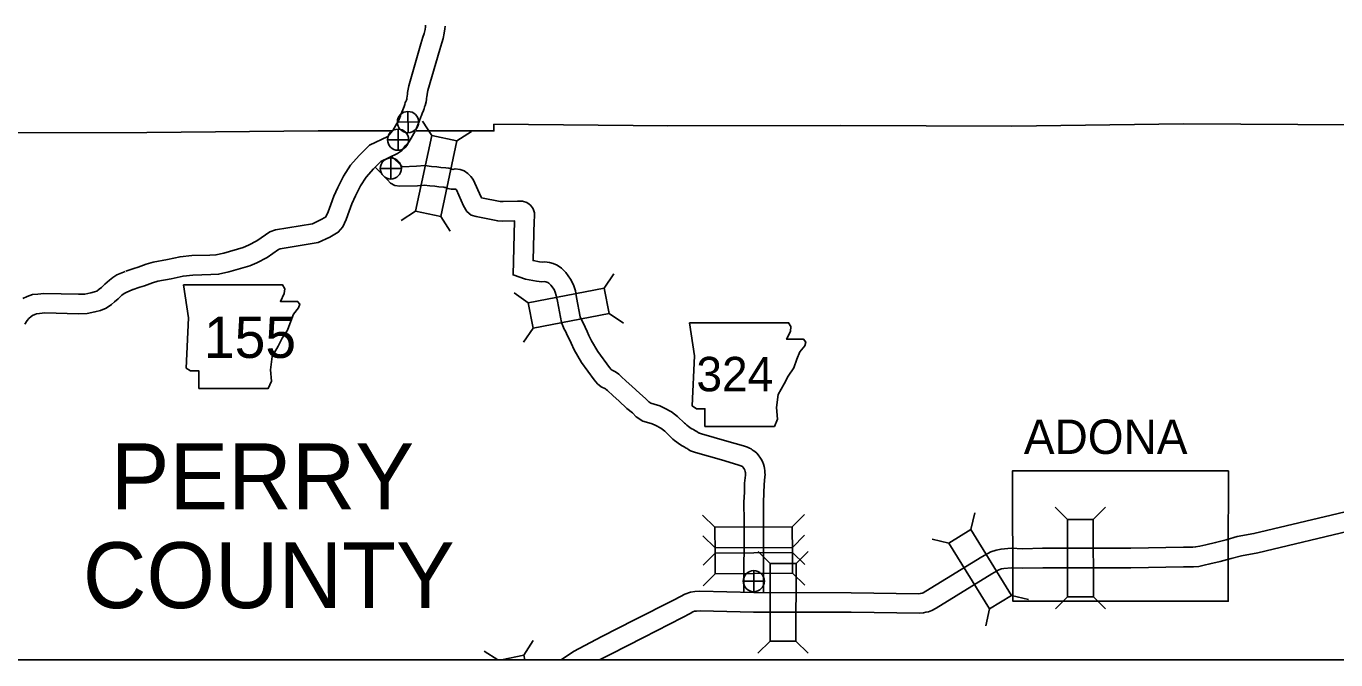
# Model space of a CAD drawing. Extents: x 1374139 to 1377472, y 1168351 to 1170484.
# Drawn here: x 1374727.2 to 1374928.1, y 1169604.3 to 1169701.5 of the extents above; entities that cross this region are included whole.
import ezdxf

# ---------------------------------------------------------------- set-up
doc = ezdxf.new("R2010")
doc.units = 0
doc.layers.add('26', color=7, linetype='Continuous')
doc.layers.add('Default', color=7, linetype='Continuous')

msp = doc.modelspace()

# ---------------------------------------------------------------- linework, layer by layer
at = {"layer": '26'}
msp.add_lwpolyline([(1374299.15, 1170388.77), (1375028.55, 1170388.77), (1375028.55, 1169604.28), (1374299.15, 1169604.28)], close=True, dxfattribs=at)
at = {"layer": 'Default'}
for p, q in [((1374785.8, 1169685.14), (1374785.73, 1169688.39)), ((1374784.14, 1169686.73), (1374787.39, 1169686.8)), ((1374784.25, 1169682.44), (1374784.25, 1169685.69)), ((1374789.42, 1169684.71), (1374787.99, 1169686.93)), ((1374782.62, 1169684.06), (1374785.87, 1169684.06)), ((1374793.29, 1169683.87), (1374795.51, 1169685.31)), ((1374781.51, 1169679.64), (1374784.76, 1169679.64)), ((1374783.14, 1169678.02), (1374783.14, 1169681.27)), ((1374786.92, 1169673.09), (1374784.7, 1169671.66)), ((1374790.79, 1169672.26), (1374792.22, 1169670.04)), ((1374815.89, 1169661.29), (1374817.38, 1169663.47)), ((1374804.22, 1169659.06), (1374802.04, 1169660.55)), ((1374816.63, 1169657.4), (1374818.82, 1169655.92)), ((1374804.97, 1169655.17), (1374803.48, 1169652.99)), ((1374886.96, 1169625.83), (1374885.09, 1169627.69)), ((1374890.92, 1169625.83), (1374892.79, 1169627.7)), ((1374832.86, 1169624.62), (1374830.98, 1169626.47)), ((1374844.74, 1169624.7), (1374846.6, 1169626.58)), ((1374872.15, 1169624.27), (1374872.76, 1169626.84)), ((1374832.88, 1169621.45), (1374831, 1169623.3)), ((1374844.76, 1169621.53), (1374846.61, 1169623.41)), ((1374868.78, 1169622.19), (1374866.21, 1169622.8)), ((1374832.89, 1169620.66), (1374831.04, 1169618.78)), ((1374841.36, 1169619.04), (1374839.5, 1169620.91)), ((1374844.77, 1169620.74), (1374846.65, 1169618.89)), ((1374845.32, 1169619.04), (1374847.19, 1169620.9)), ((1374832.91, 1169617.49), (1374831.05, 1169615.61)), ((1374838.83, 1169614.73), (1374838.83, 1169617.98)), ((1374844.79, 1169617.57), (1374846.67, 1169615.72)), ((1374837.21, 1169616.35), (1374840.46, 1169616.35)), ((1374878.39, 1169614.16), (1374880.96, 1169613.55)), ((1374886.98, 1169613.95), (1374885.11, 1169612.08)), ((1374890.94, 1169613.95), (1374892.81, 1169612.09)), ((1374875.02, 1169612.08), (1374874.41, 1169609.51)), ((1374803.56, 1169605.01), (1374805, 1169607.22)), ((1374841.34, 1169607.16), (1374839.47, 1169605.3)), ((1374845.3, 1169607.16), (1374847.16, 1169605.29)), ((1374799.54, 1169604.28), (1374797.47, 1169605.63)), ((1374803.56, 1169605.01), (1374800.14, 1169604.28)), ((1374800.14, 1169604.28), (1374803.71, 1169604.28)), ((1374803.71, 1169604.28), (1374803.56, 1169605.01))]:
    msp.add_line(p, q, dxfattribs=at)
for points in [[(1374788.46, 1169701.61), (1374788.45, 1169701.38), (1374788.39, 1169700.96), (1374788.25, 1169700.36), (1374788.07, 1169699.78), (1374787.76, 1169698.78), (1374785.9, 1169692.31), (1374785.75, 1169691.56), (1374785.71, 1169691.32), (1374785.69, 1169691.07), (1374785.63, 1169690.74), (1374785.62, 1169690.45), (1374785.61, 1169690.4), (1374785.58, 1169690.28), (1374785.52, 1169690.13), (1374785.45, 1169689.94), (1374785.36, 1169689.76), (1374785.28, 1169689.48), (1374785.16, 1169689.15), (1374785.06, 1169688.89), (1374784.97, 1169688.66), (1374784.69, 1169687.95), (1374784.6, 1169687.7), (1374784.2, 1169686.71)], [(1374791.46, 1169701.5), (1374791.44, 1169701.08), (1374791.34, 1169700.41), (1374791.15, 1169699.57), (1374790.94, 1169698.9), (1374790.64, 1169697.92), (1374788.82, 1169691.59), (1374788.7, 1169691.03), (1374788.69, 1169690.95), (1374788.67, 1169690.69), (1374788.62, 1169690.4), (1374788.61, 1169690.25), (1374788.58, 1169689.88), (1374788.42, 1169689.31), (1374788.33, 1169689.08), (1374788.23, 1169688.8), (1374788.18, 1169688.7), (1374788.14, 1169688.54), (1374787.96, 1169688.06), (1374787.84, 1169687.77), (1374787.76, 1169687.57), (1374787.49, 1169686.87), (1374787.39, 1169686.59), (1374786.98, 1169685.58)], [(1374784.29, 1169686.9), (1374783.87, 1169686.18), (1374783.46, 1169685.48), (1374783.44, 1169685.46)], [(1374931.08, 1169686.32), (1374904.76, 1169686.49), (1374878.41, 1169686.14), (1374852.12, 1169686.23), (1374825.63, 1169686.17), (1374798.95, 1169686.44), (1374798.96, 1169685.42), (1374786.98, 1169685.41)], [(1374745.68, 1169685.19), (1374721.33, 1169685.12)], [(1374783.39, 1169685.41), (1374783.09, 1169685.08), (1374782.7, 1169684.56), (1374779.85, 1169683.23), (1374778.3, 1169681.62), (1374776.96, 1169680.13), (1374775.87, 1169678.47), (1374775.03, 1169676.74), (1374774.41, 1169675.39), (1374773.94, 1169674.13), (1374773.54, 1169672.99), (1374773.22, 1169672.35), (1374773.09, 1169672.18), (1374772.36, 1169671.76), (1374771.1, 1169671.17), (1374765.46, 1169670.22), (1374764.56, 1169669.93), (1374762.6, 1169668.55), (1374761.32, 1169667.91), (1374760.47, 1169667.55), (1374757.53, 1169666.68), (1374756.31, 1169666.4), (1374755.39, 1169666.36), (1374752.6, 1169666.3), (1374750.79, 1169666.12), (1374748.86, 1169665.68), (1374746.68, 1169665.29), (1374745.62, 1169664.98), (1374744.36, 1169664.5), (1374743.71, 1169664.3), (1374742.47, 1169663.89)], [(1374786.88, 1169685.39), (1374786.46, 1169684.67), (1374785.88, 1169683.67), (1374785.41, 1169683.17), (1374784.8, 1169682.33), (1374784.17, 1169681.93), (1374781.62, 1169680.74), (1374780.49, 1169679.58), (1374779.34, 1169678.29), (1374778.49, 1169676.99), (1374777.74, 1169675.45), (1374777.18, 1169674.24), (1374776.77, 1169673.11), (1374776.31, 1169671.81), (1374775.75, 1169670.71), (1374775.07, 1169669.87), (1374773.76, 1169669.1), (1374772, 1169668.28), (1374766.18, 1169667.3), (1374765.92, 1169667.21), (1374764.14, 1169665.97), (1374762.57, 1169665.19), (1374761.49, 1169664.72), (1374758.29, 1169663.78), (1374756.72, 1169663.42), (1374755.5, 1169663.36), (1374752.78, 1169663.3), (1374751.27, 1169663.15), (1374749.46, 1169662.74), (1374747.37, 1169662.36), (1374746.57, 1169662.13), (1374745.34, 1169661.66), (1374744.63, 1169661.45), (1374743.43, 1169661.04)], [(1374783.44, 1169685.41), (1374772.01, 1169685.41), (1374745.68, 1169685.19)], [(1374826.41, 1169638.15), (1374826.17, 1169638.37), (1374825.18, 1169639.34), (1374824.58, 1169639.79), (1374823.78, 1169640.21), (1374823.25, 1169640.46), (1374822.71, 1169640.64), (1374821.81, 1169640.87), (1374820.8, 1169641.55), (1374820.21, 1169642.16), (1374819.36, 1169642.85), (1374818.13, 1169644.01), (1374817.23, 1169644.78), (1374816.37, 1169645.6), (1374816.2, 1169645.77), (1374816.1, 1169645.84), (1374815.43, 1169646.18), (1374814.86, 1169646.64), (1374814.34, 1169647.22), (1374812.39, 1169649.9), (1374811.28, 1169651.81), (1374810.8, 1169652.83), (1374810.55, 1169653.42), (1374810.27, 1169653.98), (1374809.94, 1169654.68), (1374809.75, 1169655.02), (1374809.33, 1169656.01), (1374808.7, 1169659.31), (1374808.53, 1169660.16), (1374808.38, 1169660.69), (1374808.18, 1169661.06), (1374807.68, 1169661.74), (1374807.37, 1169662.06), (1374807.22, 1169662.16), (1374807.08, 1169662.23), (1374806.93, 1169662.26), (1374806.67, 1169662.3), (1374806.31, 1169662.28), (1374805.47, 1169662.38), (1374803.81, 1169662.69), (1374801.9, 1169663.32), (1374802.11, 1169671.62), (1374800.35, 1169671.58), (1374799.55, 1169671.61), (1374796.25, 1169672.27), (1374795.47, 1169672.47), (1374794.78, 1169673.06), (1374794.31, 1169673.94), (1374793.21, 1169676.36), (1374793.13, 1169676.47), (1374793.12, 1169676.48), (1374792.42, 1169676.45), (1374791.87, 1169676.56), (1374791.51, 1169676.73), (1374791.45, 1169676.75), (1374791.29, 1169676.77), (1374790.5, 1169676.84), (1374789.9, 1169676.92), (1374789.1, 1169676.97), (1374788.25, 1169677.07), (1374787.24, 1169677.01), (1374784.53, 1169676.91), (1374783.77, 1169677.02), (1374783.07, 1169677.41), (1374782.62, 1169677.93), (1374780.78, 1169679.8)], [(1374828.33, 1169640.46), (1374828.21, 1169640.56), (1374827.14, 1169641.62), (1374826.18, 1169642.33), (1374825.12, 1169642.89), (1374824.39, 1169643.24), (1374823.57, 1169643.52), (1374823.05, 1169643.65), (1374822.74, 1169643.86), (1374822.24, 1169644.39), (1374821.33, 1169645.11), (1374820.14, 1169646.25), (1374819.24, 1169647.01), (1374818.49, 1169647.73), (1374818.13, 1169648.1), (1374817.61, 1169648.43), (1374817.08, 1169648.71), (1374816.93, 1169648.83), (1374816.67, 1169649.12), (1374814.91, 1169651.55), (1374813.94, 1169653.21), (1374813.54, 1169654.05), (1374813.28, 1169654.66), (1374812.97, 1169655.3), (1374812.6, 1169656.05), (1374812.45, 1169656.33), (1374812.21, 1169656.89), (1374811.64, 1169659.88), (1374811.45, 1169660.87), (1374811.18, 1169661.81), (1374810.73, 1169662.66), (1374809.98, 1169663.68), (1374809.31, 1169664.38), (1374808.68, 1169664.8), (1374808.06, 1169665.08), (1374807.47, 1169665.22), (1374806.77, 1169665.31), (1374806.41, 1169665.29), (1374805.93, 1169665.35), (1374804.96, 1169665.53), (1374805.12, 1169671.72), (1374805.16, 1169672.14), (1374805.16, 1169672.86), (1374804.97, 1169673.46), (1374804.63, 1169673.95), (1374804.34, 1169674.19), (1374804.01, 1169674.44), (1374803.32, 1169674.62), (1374802.57, 1169674.63), (1374800.36, 1169674.58), (1374799.9, 1169674.6), (1374797.05, 1169675.17), (1374797.01, 1169675.26), (1374795.78, 1169677.97), (1374795.39, 1169678.44), (1374794.97, 1169678.9), (1374794.37, 1169679.27), (1374793.77, 1169679.5), (1374792.99, 1169679.61), (1374792.66, 1169679.51), (1374792.06, 1169679.71), (1374791.57, 1169679.75), (1374790.83, 1169679.82), (1374790.19, 1169679.9), (1374789.37, 1169679.96), (1374788.35, 1169680.08), (1374787.1, 1169680.01), (1374784.86, 1169679.92), (1374784.81, 1169679.98), (1374783.36, 1169681.45)], [(1374742.36, 1169663.84), (1374741.12, 1169663.31), (1374740.49, 1169662.92), (1374739.97, 1169662.52), (1374739.28, 1169661.9), (1374738.72, 1169661.41), (1374738.4, 1169661.11), (1374738.03, 1169660.85), (1374737.69, 1169660.71), (1374737.1, 1169660.58), (1374736.19, 1169660.39), (1374735.22, 1169660.36), (1374729.89, 1169660.49), (1374728.97, 1169660.38), (1374728.18, 1169660.33), (1374727.34, 1169660.03), (1374726.7, 1169659.72)], [(1374743.55, 1169661.09), (1374742.51, 1169660.64), (1374742.21, 1169660.45), (1374741.89, 1169660.21), (1374741.28, 1169659.66), (1374740.73, 1169659.17), (1374740.28, 1169658.76), (1374739.48, 1169658.2), (1374738.61, 1169657.84), (1374737.73, 1169657.64), (1374736.54, 1169657.4), (1374735.23, 1169657.35), (1374730.03, 1169657.49), (1374729.24, 1169657.39), (1374728.79, 1169657.36), (1374728.5, 1169657.26), (1374728.17, 1169657.1), (1374727.94, 1169656.95), (1374727.61, 1169656.66), (1374727.33, 1169656.32), (1374726.98, 1169655.76)], [(1374828.33, 1169640.46), (1374828.56, 1169640.28), (1374828.8, 1169640.09), (1374829.01, 1169639.94), (1374829.23, 1169639.77), (1374829.3, 1169639.73), (1374829.57, 1169639.59), (1374829.81, 1169639.46), (1374830.1, 1169639.28), (1374830.35, 1169639.11), (1374830.36, 1169639.1), (1374830.39, 1169639.08), (1374830.48, 1169639.05), (1374830.79, 1169638.94), (1374834.7, 1169637.82), (1374837.23, 1169637.08), (1374837.88, 1169636.88), (1374838.15, 1169636.77), (1374838.41, 1169636.64), (1374838.6, 1169636.5), (1374838.76, 1169636.4), (1374839.01, 1169636.23), (1374839.3, 1169635.97), (1374839.5, 1169635.73), (1374839.61, 1169635.58), (1374839.78, 1169635.35), (1374839.96, 1169635.07), (1374840.17, 1169634.69), (1374840.31, 1169634.27), (1374840.4, 1169633.93), (1374840.48, 1169633.67), (1374840.53, 1169633.29), (1374840.54, 1169633.07), (1374840.55, 1169632.95), (1374840.56, 1169632.69), (1374840.53, 1169632.37), (1374840.42, 1169631.17), (1374840.38, 1169629.88), (1374840.3, 1169628.4), (1374840.33, 1169625.53)], [(1374826.42, 1169638.15), (1374826.68, 1169637.93), (1374827.02, 1169637.67), (1374827.24, 1169637.52), (1374827.57, 1169637.27), (1374827.83, 1169637.12), (1374828.14, 1169636.95), (1374828.31, 1169636.86), (1374828.47, 1169636.76), (1374828.59, 1169636.68), (1374828.73, 1169636.58), (1374829.11, 1169636.36), (1374829.43, 1169636.24), (1374829.87, 1169636.08), (1374833.86, 1169634.94), (1374836.37, 1169634.21), (1374836.84, 1169634.06), (1374836.88, 1169634.04), (1374836.89, 1169634.04), (1374836.93, 1169634.01), (1374837.08, 1169633.92), (1374837.14, 1169633.87), (1374837.2, 1169633.79), (1374837.32, 1169633.64), (1374837.36, 1169633.57), (1374837.41, 1169633.47), (1374837.44, 1169633.41), (1374837.5, 1169633.14), (1374837.54, 1169633.01), (1374837.54, 1169633), (1374837.55, 1169632.89), (1374837.55, 1169632.82), (1374837.55, 1169632.79), (1374837.54, 1169632.63), (1374837.42, 1169631.36), (1374837.38, 1169630.01), (1374837.3, 1169628.46), (1374837.33, 1169625.5)], [(1374930.44, 1169627.2), (1374915.58, 1169623.64), (1374913.01, 1169623.18), (1374911.3, 1169622.7), (1374909.68, 1169622.26), (1374908.18, 1169621.92), (1374907.28, 1169621.73), (1374906.63, 1169621.59), (1374906.18, 1169621.55), (1374904.77, 1169621.56), (1374896.67, 1169621.4), (1374886.46, 1169621.39), (1374883.15, 1169621.41), (1374880.12, 1169621.32), (1374878.31, 1169621.4), (1374876.78, 1169621.28), (1374876.01, 1169621.12), (1374875.18, 1169620.82), (1374873.84, 1169620.09), (1374865.25, 1169614.8), (1374864.8, 1169614.54), (1374864.66, 1169614.51), (1374864.38, 1169614.44), (1374864.17, 1169614.42), (1374853.79, 1169614.58), (1374838.83, 1169614.61), (1374830.54, 1169614.8), (1374829.79, 1169614.74), (1374829.1, 1169614.68), (1374828.24, 1169614.37), (1374827.59, 1169614.01), (1374826.51, 1169613.41), (1374820.54, 1169610.39), (1374815.51, 1169607.84), (1374811.17, 1169605.58), (1374809.3, 1169604.28)], [(1374837.31, 1169614.63), (1374837.33, 1169625.5)], [(1374840.31, 1169614.69), (1374840.33, 1169625.53)], [(1374931.14, 1169624.28), (1374916.19, 1169620.7), (1374913.68, 1169620.25), (1374912.1, 1169619.81), (1374910.4, 1169619.35), (1374908.82, 1169618.99), (1374907.91, 1169618.8), (1374907.1, 1169618.62), (1374906.31, 1169618.54), (1374904.79, 1169618.56), (1374896.7, 1169618.4), (1374886.45, 1169618.39), (1374883.18, 1169618.41), (1374880.1, 1169618.32), (1374878.36, 1169618.39), (1374877.21, 1169618.31), (1374876.84, 1169618.23), (1374876.41, 1169618.07), (1374875.34, 1169617.49), (1374866.79, 1169612.22), (1374866.15, 1169611.85), (1374865.63, 1169611.63), (1374865.25, 1169611.57), (1374864.89, 1169611.48), (1374864.3, 1169611.42), (1374853.77, 1169611.58), (1374838.79, 1169611.61), (1374830.62, 1169611.79), (1374830.02, 1169611.75), (1374829.74, 1169611.73), (1374829.5, 1169611.64), (1374829.05, 1169611.39), (1374827.91, 1169610.76), (1374821.9, 1169607.72), (1374816.88, 1169605.17), (1374815.18, 1169604.28)]]:
    msp.add_lwpolyline(points, dxfattribs=at)
for points in [[(1374789.42, 1169684.71), (1374786.92, 1169673.09), (1374790.79, 1169672.26), (1374793.29, 1169683.87)], [(1374751.31, 1169661.8), (1374752.07, 1169656.72), (1374751.73, 1169649.03), (1374752.41, 1169648.6), (1374753.68, 1169648.6), (1374753.68, 1169645.9), (1374764.34, 1169645.9), (1374764.84, 1169647), (1374764.67, 1169648.77), (1374764.93, 1169650.8), (1374765.86, 1169652.41), (1374766.45, 1169653.6), (1374767.3, 1169654.86), (1374767.8, 1169656.22), (1374768.23, 1169657.32), (1374768.99, 1169658.25), (1374769.16, 1169658.84), (1374768.82, 1169659.26), (1374766.2, 1169659.26), (1374766.79, 1169660.45), (1374766.87, 1169661.21), (1374766.52, 1169661.79)], [(1374804.97, 1169655.17), (1374816.63, 1169657.4), (1374815.89, 1169661.29), (1374804.22, 1169659.06)], [(1374828.96, 1169655.99), (1374829.72, 1169650.92), (1374829.38, 1169643.22), (1374830.06, 1169642.8), (1374831.33, 1169642.8), (1374831.33, 1169640.09), (1374841.99, 1169640.09), (1374842.49, 1169641.19), (1374842.32, 1169642.97), (1374842.58, 1169645), (1374843.51, 1169646.61), (1374844.1, 1169647.79), (1374844.95, 1169649.06), (1374845.45, 1169650.41), (1374845.88, 1169651.51), (1374846.64, 1169652.44), (1374846.81, 1169653.03), (1374846.47, 1169653.46), (1374843.85, 1169653.46), (1374844.44, 1169654.64), (1374844.52, 1169655.4), (1374844.17, 1169655.99)], [(1374905.02, 1169613.26), (1374911.63, 1169613.27), (1374911.64, 1169619.98), (1374911.66, 1169633.25), (1374905.03, 1169633.26), (1374878.54, 1169633.27), (1374878.59, 1169613.27)], [(1374890.94, 1169613.95), (1374890.92, 1169625.83), (1374886.96, 1169625.83), (1374886.98, 1169613.95)], [(1374844.74, 1169624.7), (1374832.86, 1169624.62), (1374832.89, 1169620.66), (1374844.77, 1169620.74)], [(1374868.78, 1169622.19), (1374875.02, 1169612.08), (1374878.39, 1169614.16), (1374872.15, 1169624.27)], [(1374844.76, 1169621.53), (1374832.88, 1169621.45), (1374832.91, 1169617.49), (1374844.79, 1169617.57)], [(1374845.3, 1169607.16), (1374845.32, 1169619.04), (1374841.36, 1169619.04), (1374841.34, 1169607.16)]]:
    msp.add_lwpolyline(points, close=True, dxfattribs=at)
for centre, radius in [((1374785.77, 1169686.76), 1.63), ((1374784.25, 1169684.06), 1.62), ((1374783.14, 1169679.64), 1.62), ((1374838.83, 1169616.35), 1.62)]:
    msp.add_circle(centre, radius, dxfattribs=at)

# ---------------------------------------------------------------- texts
for s, height, p in [('155', 6.336, (1374754.46, 1169650.59)), ('324', 5.28, (1374830.03, 1169645.47)), ('ADONA', 5.28, (1374880.27, 1169635.86)), ('PERRY', 10.107, (1374740.15, 1169627.37)), ('COUNTY', 10.107, (1374735.88, 1169612.21))]:
    msp.add_text(s, height=height, dxfattribs=at).set_placement(p)

doc.saveas('drawing.dxf')
